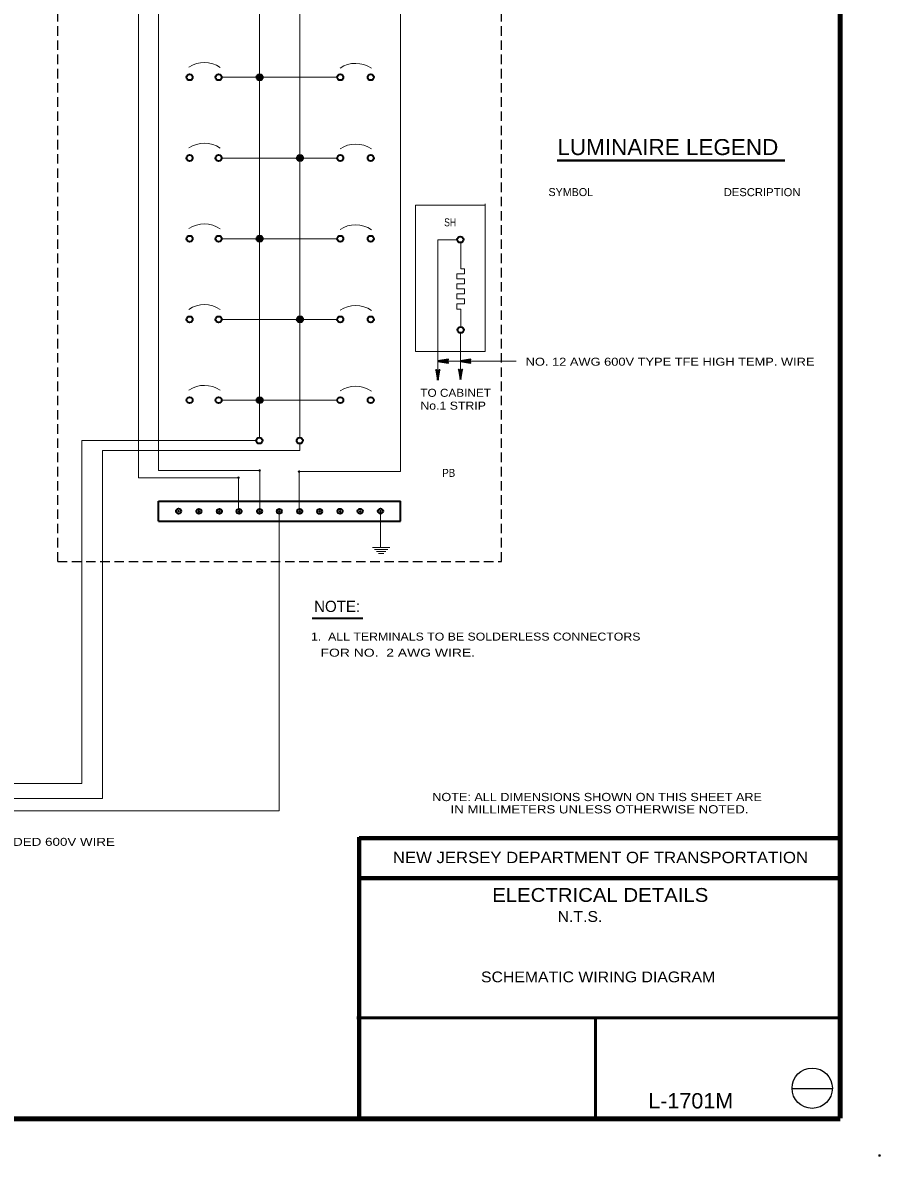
# Model space of a CAD drawing. Extents: x 312583 to 312853, y 144420 to 144585.
# Drawn here: x 312771.3 to 312852.8, y 144419.5 to 144527.2 of the extents above; entities that cross this region are included whole.
import ezdxf
from ezdxf.enums import TextEntityAlignment as Align

# ---------------------------------------------------------------- set-up
doc = ezdxf.new("R2010")
doc.units = 0
doc.header["$LTSCALE"] = 0.3
doc.header["$PDMODE"] = 32
doc.header["$PDSIZE"] = 0.15
doc.linetypes.add('MEDIUM_DASHED', pattern=[4.5, 3, -1.5])
doc.layers.add('1', color=7, linetype='Continuous', lineweight=13)
doc.layers.add('10', color=7, linetype='Continuous', lineweight=25)
doc.layers.add('2', color=7, linetype='Continuous')
doc.layers.add('5', color=7, linetype='Continuous')

msp = doc.modelspace()

# ---------------------------------------------------------------- linework, layer by layer
at = {"layer": '1', "lineweight": 158}
for p, q in [((312849, 144423.1446), (312849, 144585.0846)), ((312616.5, 144423.0846), (312849, 144423.0846))]:
    msp.add_line(p, q, dxfattribs=at)
at = {"layer": '1', "linetype": 'MEDIUM_DASHED', "lineweight": 25}
for p, q in [((312774.654, 144475.991), (312774.654, 144567.991)), ((312816.8206, 144475.991), (312816.8206, 144567.991)), ((312774.654, 144475.991), (312816.8206, 144475.991))]:
    msp.add_line(p, q, dxfattribs=at)
at = {"layer": '1'}
for p, q in [((312797.654, 144487.7823), (312797.654, 144560.3243)), ((312784.2373, 144484.6466), (312784.2373, 144557.0353)), ((312807.2373, 144484.5393), (312807.2373, 144556.997)), ((312793.8206, 144487.7746), (312793.8206, 144552.6576)), ((312782.3206, 144483.9643), (312782.3206, 144540.989)), ((312790.2173, 144521.991), (312801.2343, 144521.991)), ((312790.2173, 144514.3243), (312801.2113, 144514.3243)), ((312808.648, 144509.8546), (312815.2873, 144509.8546)), ((312808.648, 144495.9396), (312808.648, 144509.8546)), ((312815.2873, 144495.9396), (312815.2873, 144509.9773)), ((312790.2556, 144506.6576), (312801.196, 144506.6576)), ((312812.949, 144503.8133), (312812.949, 144506.305)), ((312813.3093, 144503.338), (312812.5886, 144503.338)), ((312812.5886, 144502.855), (312812.5886, 144503.338)), ((312813.3093, 144503.8133), (312812.949, 144503.8133)), ((312813.3093, 144503.338), (312813.3093, 144503.8133)), ((312813.3093, 144502.855), (312812.5886, 144502.855)), ((312813.3093, 144502.3796), (312812.5886, 144502.3796)), ((312812.5886, 144501.8966), (312812.5886, 144502.3796)), ((312813.3093, 144502.3796), (312813.3093, 144502.855)), ((312813.3093, 144501.8966), (312812.5886, 144501.8966)), ((312813.3093, 144501.4213), (312812.5886, 144501.4213)), ((312812.5886, 144500.9383), (312812.5886, 144501.4213)), ((312813.3093, 144501.4213), (312813.3093, 144501.8966)), ((312813.3093, 144500.9383), (312812.5886, 144500.9383)), ((312813.3093, 144500.463), (312812.5886, 144500.463)), ((312812.5886, 144499.98), (312812.5886, 144500.463)), ((312812.949, 144499.98), (312812.5886, 144499.98)), ((312812.949, 144498.2933), (312812.949, 144499.98)), ((312813.3093, 144500.463), (312813.3093, 144500.9383)), ((312790.2326, 144498.991), (312801.196, 144498.991)), ((312812.9183, 144497.6186), (312812.9183, 144493.287)), ((312808.648, 144495.9396), (312815.2873, 144495.9396)), ((312810.787, 144495.035), (312818.2156, 144495.035)), ((312776.954, 144487.491), (312793.491, 144487.491)), ((312776.954, 144487.491), (312776.954, 144454.9153)), ((312797.654, 144486.5326), (312797.654, 144487.2073)), ((312778.9166, 144486.5326), (312797.654, 144486.5326)), ((312778.9166, 144486.5326), (312778.9166, 144453.4816)), ((312791.835, 144483.9643), (312782.3206, 144483.9643)), ((312793.8513, 144484.6466), (312784.2373, 144484.6466)), ((312791.835, 144481.0816), (312791.835, 144483.9643)), ((312793.8513, 144481.0816), (312793.8513, 144484.6466)), ((312797.585, 144480.9666), (312797.585, 144484.5393)), ((312797.585, 144484.5393), (312807.2373, 144484.5393)), ((312805.3283, 144480.7826), (312805.3283, 144477.348)), ((312795.6913, 144480.5066), (312795.6913, 144452.3163)), ((312804.5616, 144477.348), (312806.21, 144477.348)), ((312804.7533, 144477.1563), (312806.0183, 144477.1563)), ((312804.945, 144476.957), (312805.8266, 144476.957)), ((312805.1366, 144476.7653), (312805.635, 144476.7653)), ((312721.5584, 144454.9153), (312776.954, 144454.9153)), ((312721.6236, 144452.3163), (312795.6913, 144452.3163))]:
    msp.add_line(p, q, dxfattribs=at)
at = {"layer": '1', "lineweight": 40}
msp.add_line((312822.1235, 144514.1018), (312843.7583, 144514.1018), dxfattribs=at)
at = {"layer": '1', "lineweight": 35}
for p, q in [((312784.2373, 144481.741), (312807.2373, 144481.741)), ((312784.2373, 144479.8243), (312784.2373, 144481.741)), ((312807.2373, 144479.8243), (312807.2373, 144481.741)), ((312807.2373, 144479.8243), (312807.2373, 144481.741)), ((312784.2373, 144479.8243), (312807.2373, 144479.8243)), ((312798.8365, 144470.6132), (312803.6556, 144470.6132))]:
    msp.add_line(p, q, dxfattribs=at)
at = {"layer": '1', "lineweight": 80}
for p, q in [((312803.31, 144423.1446), (312803.31, 144449.8146)), ((312803.31, 144449.7246), (312849, 144449.7246)), ((312803.31, 144445.9146), (312849, 144445.9146))]:
    msp.add_line(p, q, dxfattribs=at)
at = {"layer": '1', "lineweight": 53}
for p, q in [((312849, 144432.6666), (312803.0767, 144432.6666)), ((312825.7547, 144432.6666), (312825.7547, 144423.1446))]:
    msp.add_line(p, q, dxfattribs=at)
at = {"layer": '1'}
for points in [[(312812.5733, 144506.558), (312810.787, 144506.558), (312810.787, 144493.2333)], [(312790.202, 144491.3243), (312793.767, 144491.3243), (312801.219, 144491.3243)], [(312717.656, 144453.4816), (312744.0946, 144453.4816), (312778.9166, 144453.4816)]]:
    msp.add_lwpolyline(points, dxfattribs=at)
at = {"layer": '1', "lineweight": 35}
for points in [[(312810.787, 144495.035), (312811.753, 144494.874), (312811.431, 144495.035), (312811.753, 144495.196)], [(312812.9183, 144495.035), (312813.8843, 144494.874), (312813.5623, 144495.035), (312813.8843, 144495.196)], [(312810.787, 144493.2333), (312810.948, 144494.1993), (312810.787, 144493.8773), (312810.626, 144494.1993)], [(312812.9183, 144493.287), (312813.0793, 144494.253), (312812.9183, 144493.931), (312812.7573, 144494.253)]]:
    msp.add_lwpolyline(points, close=True, dxfattribs=at)
for centre, radius in [((312787.1813, 144521.9912), 0.2897), ((312789.9413, 144521.9912), 0.2897), ((312793.8362, 144521.991), 0.2897), ((312793.836, 144521.991), 0.23), ((312793.836, 144521.991), 0.1533), ((312793.836, 144521.991), 0.0767), ((312801.5026, 144521.9912), 0.2897), ((312804.4006, 144521.9912), 0.2897), ((312787.1813, 144514.3245), 0.2897), ((312789.9413, 144514.3245), 0.2897), ((312797.6695, 144514.3243), 0.2897), ((312797.6693, 144514.3243), 0.23), ((312797.6693, 144514.3243), 0.1533), ((312797.6693, 144514.3243), 0.0767), ((312801.5026, 144514.3245), 0.2897), ((312804.4006, 144514.3245), 0.2897), ((312787.1813, 144506.6579), 0.2897), ((312789.9413, 144506.6579), 0.2897), ((312793.8362, 144506.6576), 0.2897), ((312793.836, 144506.6576), 0.23), ((312793.836, 144506.6576), 0.1533), ((312793.836, 144506.6576), 0.0767), ((312801.5026, 144506.6579), 0.2897), ((312804.4006, 144506.6579), 0.2897), ((312812.9106, 144506.5807), 0.2897), ((312787.1813, 144498.9912), 0.2897), ((312789.9413, 144498.9912), 0.2897), ((312797.6695, 144498.991), 0.2897), ((312797.6693, 144498.991), 0.23), ((312797.6693, 144498.991), 0.1533), ((312797.6693, 144498.991), 0.0767), ((312801.5026, 144498.9912), 0.2897), ((312804.4006, 144498.9912), 0.2897), ((312812.9492, 144498.002), 0.2897), ((312787.1813, 144491.3245), 0.2897), ((312789.9413, 144491.3245), 0.2897), ((312793.8362, 144491.3243), 0.2897), ((312793.836, 144491.3243), 0.23), ((312793.836, 144491.3243), 0.1533), ((312793.836, 144491.3243), 0.0767), ((312801.5026, 144491.3245), 0.2897), ((312804.4006, 144491.3245), 0.2897), ((312793.8206, 144487.4907), 0.2897), ((312797.6537, 144487.491), 0.2897), ((312786.1386, 144480.7826), 0.2396), ((312788.0783, 144480.7673), 0.2396), ((312790.018, 144480.7673), 0.2396), ((312791.8886, 144480.7673), 0.2396), ((312793.8436, 144480.7673), 0.2396), ((312795.7143, 144480.7673), 0.2396), ((312797.654, 144480.7673), 0.2396), ((312799.5476, 144480.7596), 0.2396), ((312801.4873, 144480.775), 0.2396), ((312803.3963, 144480.775), 0.2396), ((312805.3283, 144480.7826), 0.2396)]:
    msp.add_circle(centre, radius, dxfattribs=at)
at = {"layer": '1'}
for centre in [(312788.5959, 144520.7184), (312802.9632, 144520.6341), (312788.5959, 144513.0518), (312802.9632, 144512.9674), (312788.5959, 144505.3851), (312802.9632, 144505.3008), (312788.5959, 144497.7184), (312802.9632, 144497.6341), (312788.5959, 144490.0518), (312802.9632, 144489.9674)]:
    msp.add_arc(centre, 2.6791, 55.78717, 123.62519, dxfattribs=at)
for p in [(312791.835, 144483.9643), (312793.8513, 144484.6466), (312797.585, 144484.5393), (312786.1386, 144480.7826), (312788.0783, 144480.7673), (312790.018, 144480.7673), (312791.8886, 144480.7673), (312793.8436, 144480.7673), (312795.7143, 144480.7673), (312797.654, 144480.7673), (312799.5476, 144480.7596), (312801.4873, 144480.775), (312803.3963, 144480.775), (312805.3283, 144480.7826), (312852.75, 144419.5846)]:
    msp.add_point(p, dxfattribs=at)
at = {"layer": '10'}
msp.add_line((312844.4384, 144425.9659), (312848.2794, 144425.9659), dxfattribs=at)
msp.add_circle((312846.3494, 144425.9805), 1.9159, dxfattribs=at)

# ---------------------------------------------------------------- texts
at = {"layer": '1'}
for s, height, width, p in [('LUMINAIRE LEGEND', 1.52, 1.05, (312822.1392, 144514.6024)), ('DESCRIPTION', 0.76, 1.05, (312837.9409, 144510.7008)), ('SH', 0.76, 0.8, (312811.379, 144507.8373)), ('NO. 12 AWG 600V TYPE TFE HIGH TEMP. WIRE', 0.76, 1.2, (312819.1218, 144494.597)), ('TO CABINET', 0.76, 1.1, (312809.1139, 144491.6434)), ('No.1 STRIP', 0.76, 1.15, (312809.1139, 144490.4234)), ('PB', 0.76, 0.9, (312811.2056, 144484.042)), ('1.  ALL TERMINALS TO BE SOLDERLESS CONNECTORS', 0.76, 1.15, (312798.7235, 144468.4905)), ('    FOR NO.  2 AWG WIRE.', 0.76, 1.3, (312798.1624, 144466.9629)), ('NOTE: ALL DIMENSIONS SHOWN ON THIS SHEET ARE', 0.78, 1.15, (312810.2501, 144453.2462)), ('     IN MILLIMETERS UNLESS OTHERWISE NOTED.', 0.78, 1.2, (312810.25, 144452.0762)), ('NO.      AWG STRANDED 600V WIRE', 0.76, 1.25, (312758.352, 144448.9976))]:
    msp.add_text(s, height=height, dxfattribs=dict(at, width=width)).set_placement(p)
for s, height, p in [('SYMBOL', 0.76, (312821.2934, 144510.7085)), ('NOTE:', 1.07, (312799.0203, 144471.207))]:
    msp.add_text(s, height=height, dxfattribs=at).set_placement(p)
at = {"layer": '1', "width": 1.1}
for s, height, p in [('NEW JERSEY DEPARTMENT OF TRANSPORTATION', 1.08, (312826.2285, 144447.3546)), ('ELECTRICAL DETAILS', 1.315, (312826.2109, 144443.6759))]:
    msp.add_text(s, height=height, dxfattribs=at).set_placement(p, align=Align.CENTER)
at = {"layer": '2', "width": 1.1}
for s, p in [('    N.T.S.  ', (312823.87, 144441.778)), ('SCHEMATIC WIRING DIAGRAM ', (312826.2147, 144436.0399))]:
    msp.add_text(s, height=1.02, dxfattribs=at).set_placement(p, align=Align.CENTER)
at = {"layer": '5', "width": 1.05}
msp.add_text('L-1701M ', height=1.457, dxfattribs=at).set_placement((312835.0933, 144424.0569), align=Align.CENTER)

doc.saveas('drawing.dxf')
